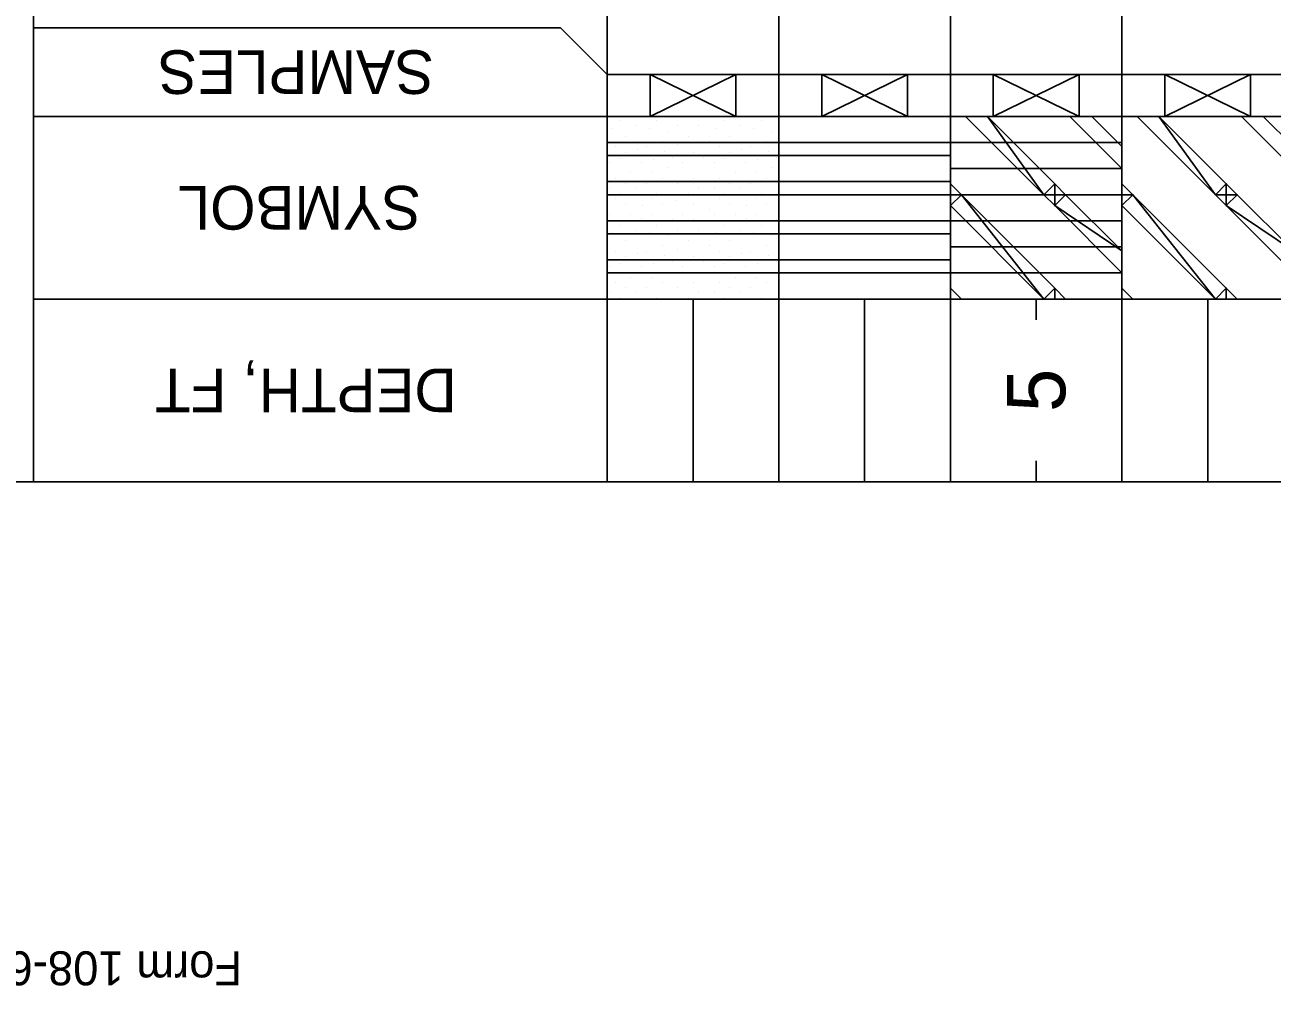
# Model space of a CAD drawing. Extents: x 1313964 to 1316843, y 2087046 to 2096619.
# Drawn here: x 1314180.68 to 1314195.22, y 2089867.54 to 2089878.76 of the extents above; entities that cross this region are included whole.
import ezdxf

# ---------------------------------------------------------------- set-up
doc = ezdxf.new("R2010")
doc.units = 0
doc.layers.add('B-Sub-Contour', color=7, linetype='Continuous')
doc.layers.add('Default', color=7, linetype='Continuous')

# ---------------------------------------------------------------- blocks, each defined once
blk = doc.blocks.new('POINT_DISPLAY')
at = {"layer": 'Default'}
blk.add_line((0, 0), (0, 0), dxfattribs=at)

msp = doc.modelspace()

# ---------------------------------------------------------------- linework, layer by layer
at = {"layer": 'B-Sub-Contour'}
for points in [[(1314234.904, 2089873.434), (1314234.904, 2089916.306), (1314173.485, 2089916.306), (1314173.485, 2089873.434), (1314234.904, 2089873.434)], [(1314180.782, 2089873.434), (1314180.782, 2089916.306)], [(1314187.471, 2089873.434), (1314187.471, 2089916.306)], [(1314189.471, 2089878.178), (1314189.471, 2089894.049)], [(1314191.471, 2089878.178), (1314191.471, 2089894.049)], [(1314193.471, 2089878.178), (1314193.471, 2089894.049)], [(1314186.924, 2089878.725), (1314180.782, 2089878.725)], [(1314187.471, 2089878.178), (1314186.924, 2089878.725)], [(1314232.471, 2089878.178), (1314187.471, 2089878.178)], [(1314187.971, 2089877.691), (1314188.971, 2089878.178)], [(1314188.971, 2089877.691), (1314187.971, 2089878.178)], [(1314187.971, 2089877.691), (1314187.971, 2089878.178)], [(1314188.971, 2089877.691), (1314188.971, 2089878.178)], [(1314189.471, 2089877.691), (1314189.471, 2089878.178)], [(1314189.971, 2089877.691), (1314190.971, 2089878.178)], [(1314190.971, 2089877.691), (1314189.971, 2089878.178)], [(1314189.971, 2089877.691), (1314189.971, 2089878.178)], [(1314190.971, 2089877.691), (1314190.971, 2089878.178)], [(1314191.471, 2089877.691), (1314191.471, 2089878.178)], [(1314191.971, 2089877.691), (1314192.971, 2089878.178)], [(1314192.971, 2089877.691), (1314191.971, 2089878.178)], [(1314191.971, 2089877.691), (1314191.971, 2089878.178)], [(1314192.971, 2089877.691), (1314192.971, 2089878.178)], [(1314193.471, 2089877.691), (1314193.471, 2089878.178)], [(1314193.971, 2089877.691), (1314194.971, 2089878.178)], [(1314194.971, 2089877.691), (1314193.971, 2089878.178)], [(1314193.971, 2089877.691), (1314193.971, 2089878.178)], [(1314194.971, 2089877.691), (1314194.971, 2089878.178)], [(1314232.471, 2089877.691), (1314180.782, 2089877.691)], [(1314189.471, 2089875.563), (1314189.471, 2089877.691)], [(1314191.471, 2089875.563), (1314191.471, 2089877.691)], [(1314193.471, 2089875.563), (1314193.471, 2089877.691)], [(1314193.471, 2089877.387), (1314191.471, 2089877.387)], [(1314193.471, 2089877.083), (1314191.471, 2089877.083)], [(1314193.471, 2089876.779), (1314191.471, 2089876.779)], [(1314193.471, 2089876.475), (1314191.471, 2089876.475)], [(1314193.471, 2089876.171), (1314191.471, 2089876.171)], [(1314193.471, 2089875.867), (1314191.471, 2089875.867)], [(1314232.471, 2089875.563), (1314180.782, 2089875.563)], [(1314187.471, 2089875.319), (1314187.471, 2089875.563)], [(1314187.471, 2089875.319), (1314187.471, 2089875.563)], [(1314188.471, 2089873.434), (1314188.471, 2089875.563)], [(1314189.471, 2089873.434), (1314189.471, 2089875.563)], [(1314189.471, 2089873.434), (1314189.471, 2089875.563)], [(1314190.471, 2089873.434), (1314190.471, 2089875.563)], [(1314191.471, 2089873.434), (1314191.471, 2089875.563)], [(1314191.471, 2089873.434), (1314191.471, 2089875.563)], [(1314192.471, 2089875.319), (1314192.471, 2089875.563)], [(1314193.471, 2089873.434), (1314193.471, 2089875.563)], [(1314193.471, 2089873.434), (1314193.471, 2089875.563)], [(1314194.471, 2089873.434), (1314194.471, 2089875.563)], [(1314187.471, 2089873.434), (1314187.471, 2089873.678)], [(1314187.471, 2089873.434), (1314187.471, 2089873.678)], [(1314192.471, 2089873.434), (1314192.471, 2089873.678)]]:
    msp.add_lwpolyline(points, dxfattribs=at)
for points in [[(1314192.56, 2089876.779), (1314191.903, 2089877.691), (1314191.647, 2089877.691), (1314192.56, 2089876.779)], [(1314192.56, 2089876.779), (1314192.687, 2089876.907), (1314191.903, 2089877.691), (1314192.56, 2089876.779)], [(1314193.119, 2089877.691), (1314192.864, 2089877.691), (1314193.471, 2089877.084), (1314193.471, 2089877.339)], [(1314194.56, 2089876.779), (1314193.903, 2089877.691), (1314193.647, 2089877.691), (1314194.56, 2089876.779)], [(1314194.56, 2089876.779), (1314194.687, 2089876.907), (1314193.903, 2089877.691), (1314194.56, 2089876.779)], [(1314195.119, 2089877.691), (1314194.864, 2089877.691), (1314195.471, 2089877.084), (1314195.471, 2089877.339)], [(1314189.471, 2089877.235), (1314189.471, 2089877.387), (1314187.471, 2089877.387), (1314187.471, 2089877.235)], [(1314191.471, 2089877.235), (1314191.471, 2089877.387), (1314189.471, 2089877.387), (1314189.471, 2089877.235)], [(1314189.471, 2089876.779), (1314189.471, 2089876.931), (1314187.471, 2089876.931), (1314187.471, 2089876.779)], [(1314191.471, 2089876.779), (1314191.471, 2089876.931), (1314189.471, 2089876.931), (1314189.471, 2089876.779)], [(1314191.599, 2089876.779), (1314191.471, 2089876.779), (1314191.471, 2089876.907), (1314191.599, 2089876.779)], [(1314192.56, 2089876.779), (1314192.687, 2089876.779), (1314192.687, 2089876.907), (1314192.56, 2089876.779)], [(1314192.815, 2089876.779), (1314192.687, 2089876.779), (1314192.687, 2089876.907), (1314192.815, 2089876.779)], [(1314193.599, 2089876.779), (1314193.471, 2089876.779), (1314193.471, 2089876.907), (1314193.599, 2089876.779)], [(1314194.56, 2089876.779), (1314194.687, 2089876.779), (1314194.687, 2089876.907), (1314194.56, 2089876.779)], [(1314194.815, 2089876.779), (1314194.687, 2089876.779), (1314194.687, 2089876.907), (1314194.815, 2089876.779)], [(1314191.599, 2089876.779), (1314191.471, 2089876.779), (1314191.471, 2089876.651), (1314191.599, 2089876.779)], [(1314192.56, 2089875.563), (1314191.599, 2089876.779), (1314191.471, 2089876.651), (1314192.56, 2089875.563)], [(1314192.56, 2089875.563), (1314192.687, 2089875.69), (1314191.599, 2089876.779), (1314192.56, 2089875.563)], [(1314192.687, 2089876.779), (1314192.687, 2089876.651), (1314192.56, 2089876.779), (1314192.687, 2089876.779)], [(1314192.815, 2089876.779), (1314192.687, 2089876.779), (1314192.687, 2089876.651), (1314192.815, 2089876.779)], [(1314192.687, 2089876.651), (1314193.471, 2089876.123), (1314192.815, 2089876.779), (1314192.687, 2089876.651)], [(1314193.599, 2089876.779), (1314193.471, 2089876.779), (1314193.471, 2089876.651), (1314193.599, 2089876.779)], [(1314194.56, 2089875.563), (1314193.599, 2089876.779), (1314193.471, 2089876.651), (1314194.56, 2089875.563)], [(1314194.56, 2089875.563), (1314194.687, 2089875.69), (1314193.599, 2089876.779), (1314194.56, 2089875.563)], [(1314194.687, 2089876.779), (1314194.687, 2089876.651), (1314194.56, 2089876.779), (1314194.687, 2089876.779)], [(1314194.815, 2089876.779), (1314194.687, 2089876.779), (1314194.687, 2089876.651), (1314194.815, 2089876.779)], [(1314194.687, 2089876.651), (1314195.471, 2089876.123), (1314194.815, 2089876.779), (1314194.687, 2089876.651)], [(1314192.687, 2089876.651), (1314193.471, 2089875.868), (1314193.471, 2089876.123), (1314192.687, 2089876.651)], [(1314194.687, 2089876.651), (1314195.471, 2089875.868), (1314195.471, 2089876.123), (1314194.687, 2089876.651)], [(1314189.471, 2089876.323), (1314189.471, 2089876.475), (1314187.471, 2089876.475), (1314187.471, 2089876.323)], [(1314191.471, 2089876.323), (1314191.471, 2089876.475), (1314189.471, 2089876.475), (1314189.471, 2089876.323)], [(1314189.471, 2089875.867), (1314189.471, 2089876.019), (1314187.471, 2089876.019), (1314187.471, 2089875.867)], [(1314191.471, 2089875.867), (1314191.471, 2089876.019), (1314189.471, 2089876.019), (1314189.471, 2089875.867)], [(1314191.599, 2089875.563), (1314191.471, 2089875.563), (1314191.471, 2089875.69), (1314191.599, 2089875.563)], [(1314192.56, 2089875.563), (1314192.687, 2089875.563), (1314192.687, 2089875.69), (1314192.56, 2089875.563)], [(1314192.815, 2089875.563), (1314192.687, 2089875.563), (1314192.687, 2089875.69), (1314192.815, 2089875.563)], [(1314193.599, 2089875.563), (1314193.471, 2089875.563), (1314193.471, 2089875.69), (1314193.599, 2089875.563)], [(1314194.56, 2089875.563), (1314194.687, 2089875.563), (1314194.687, 2089875.69), (1314194.56, 2089875.563)], [(1314194.815, 2089875.563), (1314194.687, 2089875.563), (1314194.687, 2089875.69), (1314194.815, 2089875.563)]]:
    msp.add_lwpolyline(points, close=True, dxfattribs=at)

# ---------------------------------------------------------------- block references
at = {"layer": 'B-Sub-Contour', "xscale": 0.019951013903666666, "yscale": 0.019951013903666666, "rotation": 90}
for p in [(1314187.623, 2089877.641), (1314188.049, 2089877.641), (1314188.84, 2089877.641), (1314189.265, 2089877.641), (1314187.532, 2089877.555), (1314187.684, 2089877.458), (1314187.806, 2089877.58), (1314187.961, 2089877.552), (1314188.171, 2089877.519), (1314188.292, 2089877.58), (1314188.414, 2089877.458), (1314188.535, 2089877.58), (1314188.748, 2089877.555), (1314188.9, 2089877.458), (1314189.022, 2089877.58), (1314189.177, 2089877.552), (1314189.387, 2089877.519), (1314187.563, 2089877.337), (1314187.927, 2089877.337), (1314188.11, 2089877.398), (1314188.292, 2089877.359), (1314188.657, 2089877.398), (1314188.779, 2089877.337), (1314189.144, 2089877.337), (1314189.326, 2089877.398), (1314187.618, 2089877.196), (1314187.684, 2089877.276), (1314187.822, 2089877.307), (1314188.008, 2089877.188), (1314188.135, 2089877.282), (1314188.231, 2089877.215), (1314188.475, 2089877.276), (1314188.596, 2089877.215), (1314188.834, 2089877.196), (1314188.9, 2089877.276), (1314189.039, 2089877.307), (1314189.224, 2089877.188), (1314189.351, 2089877.282), (1314189.448, 2089877.215), (1314187.502, 2089877.154), (1314187.745, 2089877.033), (1314187.867, 2089877.154), (1314187.988, 2089877.033), (1314188.171, 2089877.094), (1314188.353, 2089877.154), (1314188.718, 2089877.154), (1314188.961, 2089877.033), (1314189.083, 2089877.154), (1314189.204, 2089877.033), (1314189.387, 2089877.094), (1314187.563, 2089876.972), (1314187.684, 2089876.911), (1314187.927, 2089876.911), (1314188.11, 2089876.972), (1314188.292, 2089876.911), (1314188.475, 2089876.972), (1314188.779, 2089876.972), (1314188.9, 2089876.911), (1314189.144, 2089876.911), (1314189.326, 2089876.972), (1314187.502, 2089876.85), (1314187.623, 2089876.79), (1314187.806, 2089876.85), (1314187.867, 2089876.768), (1314188.049, 2089876.79), (1314188.414, 2089876.79), (1314188.535, 2089876.85), (1314188.596, 2089876.776), (1314188.718, 2089876.85), (1314188.84, 2089876.79), (1314189.022, 2089876.85), (1314189.083, 2089876.768), (1314189.265, 2089876.79), (1314187.563, 2089876.729), (1314187.684, 2089876.668), (1314187.883, 2089876.648), (1314187.988, 2089876.729), (1314188.11, 2089876.668), (1314188.278, 2089876.712), (1314188.475, 2089876.668), (1314188.657, 2089876.607), (1314188.779, 2089876.729), (1314188.9, 2089876.668), (1314189.099, 2089876.648), (1314189.204, 2089876.729), (1314189.326, 2089876.668), (1314187.502, 2089876.546), (1314187.745, 2089876.546), (1314187.875, 2089876.502), (1314187.988, 2089876.546), (1314188.231, 2089876.485), (1314188.353, 2089876.546), (1314188.475, 2089876.488), (1314188.718, 2089876.546), (1314188.961, 2089876.546), (1314189.091, 2089876.502), (1314189.204, 2089876.546), (1314189.448, 2089876.485), (1314187.532, 2089876.339), (1314187.623, 2089876.425), (1314187.806, 2089876.364), (1314187.961, 2089876.336), (1314188.049, 2089876.425), (1314188.171, 2089876.303), (1314188.292, 2089876.364), (1314188.535, 2089876.364), (1314188.748, 2089876.339), (1314188.84, 2089876.425), (1314189.022, 2089876.364), (1314189.177, 2089876.336), (1314189.265, 2089876.425), (1314189.387, 2089876.303), (1314187.684, 2089876.242), (1314188.11, 2089876.181), (1314188.414, 2089876.242), (1314188.657, 2089876.181), (1314188.9, 2089876.242), (1314189.326, 2089876.181), (1314187.563, 2089876.121), (1314187.684, 2089876.06), (1314187.822, 2089876.09), (1314187.927, 2089876.121), (1314188.135, 2089876.066), (1314188.292, 2089876.143), (1314188.475, 2089876.06), (1314188.779, 2089876.121), (1314188.9, 2089876.06), (1314189.039, 2089876.09), (1314189.144, 2089876.121), (1314189.351, 2089876.066), (1314187.502, 2089875.938), (1314187.618, 2089875.98), (1314187.867, 2089875.938), (1314188.008, 2089875.972), (1314188.171, 2089875.877), (1314188.231, 2089875.999), (1314188.353, 2089875.938), (1314188.596, 2089875.999), (1314188.718, 2089875.938), (1314188.834, 2089875.98), (1314189.083, 2089875.938), (1314189.224, 2089875.972), (1314189.387, 2089875.877), (1314189.448, 2089875.999), (1314187.563, 2089875.756), (1314187.745, 2089875.817), (1314187.988, 2089875.817), (1314188.11, 2089875.756), (1314188.475, 2089875.756), (1314188.779, 2089875.756), (1314188.961, 2089875.817), (1314189.204, 2089875.817), (1314189.326, 2089875.756), (1314187.502, 2089875.634), (1314187.623, 2089875.573), (1314187.684, 2089875.695), (1314187.806, 2089875.634), (1314187.927, 2089875.695), (1314188.049, 2089875.573), (1314188.292, 2089875.695), (1314188.414, 2089875.573), (1314188.535, 2089875.634), (1314188.718, 2089875.634), (1314188.84, 2089875.573), (1314188.9, 2089875.695), (1314189.022, 2089875.634), (1314189.144, 2089875.695), (1314189.265, 2089875.573)]:
    msp.add_blockref('POINT_DISPLAY', p, dxfattribs=at)

# ---------------------------------------------------------------- texts
at = {"layer": 'B-Sub-Contour'}
for s, height, rotation, p in [('SAMPLES', 0.509, 180, (1314185.45, 2089878.462)), ('SYMBOL', 0.509, 180, (1314185.299, 2089876.881)), ('DEPTH, FT', 0.509, 180, (1314185.715, 2089874.753)), ('5', 0.679, 90, (1314192.811, 2089874.246)), ('Form 108-6(74) Job No. 20-083', 0.39588, 180, (1314183.215, 2089867.961))]:
    msp.add_text(s, height=height, rotation=rotation, dxfattribs=at).set_placement(p)

doc.saveas('drawing.dxf')
